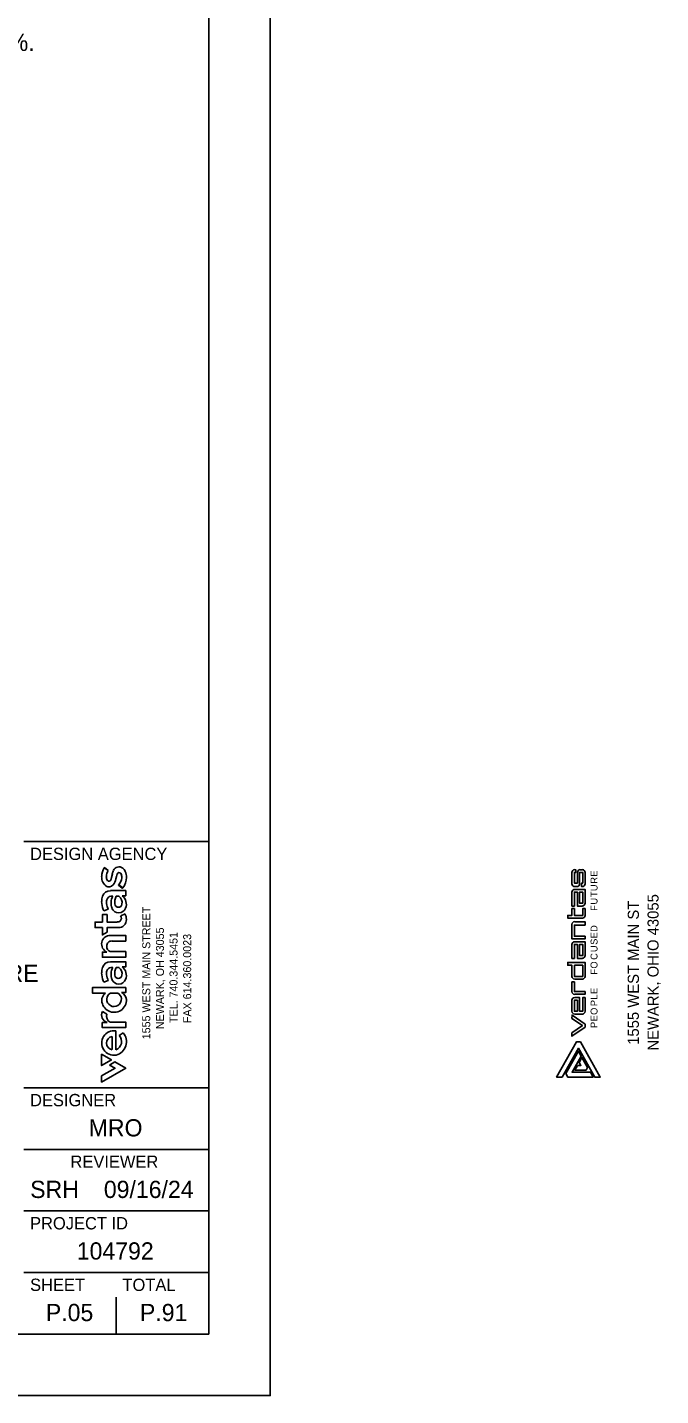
# Model space of a CAD drawing. Extents: x 0 to 46.4, y 0 to 22.
# Drawn here: x 32.03 to 37.17, y 0 to 11.11 of the extents above; entities that cross this region are included whole.
import ezdxf

# ---------------------------------------------------------------- set-up
doc = ezdxf.new("R2010")
doc.units = 0
for name, color, linetype in [('CS-ANNO-TTLB-LOGO', 7, 'Continuous'), ('Default', 7, 'Continuous'), ('SH_Border', 7, 'Continuous'), ('SH_Cut_Line', 7, 'Continuous'), ('SH_Data', 7, 'Continuous'), ('SH_Text', 7, 'Continuous')]:
    doc.layers.add(name, color=color, linetype=linetype)

msp = doc.modelspace()

# ---------------------------------------------------------------- linework, layer by layer
at = {"layer": 'CS-ANNO-TTLB-LOGO'}
for p, q in [((36.449, 4.249), (36.449, 4.156)), ((36.48, 4.271), (36.472, 4.271)), ((36.534, 4.271), (36.517, 4.271)), ((36.556, 4.156), (36.556, 4.249)), ((36.472, 4.134), (36.489, 4.134)), ((36.449, 3.976), (36.449, 4.089)), ((36.449, 3.551), (36.449, 3.664)), ((36.472, 3.383), (36.534, 3.383)), ((36.556, 3.121), (36.556, 3.233)), ((36.449, 3.211), (36.449, 3.121)), ((36.472, 3.098), (36.534, 3.098))]:
    msp.add_line(p, q, dxfattribs=at)
for points in [[(36.494, 4.249), (36.494, 4.162), (36.469, 4.162), (36.469, 4.249), (36.48, 4.249), (36.48, 4.271)], [(36.511, 4.156), (36.511, 4.249), (36.537, 4.249), (36.537, 4.162), (36.528, 4.162), (36.528, 4.134), (36.534, 4.134)], [(36.534, 3.976), (36.494, 3.976), (36.494, 4.089), (36.469, 4.089), (36.469, 3.976), (36.449, 3.976)], [(36.472, 4.111), (36.556, 4.111), (36.556, 3.999)], [(36.415, 3.9), (36.449, 3.9), (36.449, 3.956), (36.469, 3.956), (36.469, 3.9), (36.537, 3.9), (36.537, 3.956), (36.556, 3.956), (36.556, 3.9)], [(36.534, 3.878), (36.415, 3.878), (36.415, 3.9)], [(36.449, 3.827), (36.449, 3.709), (36.556, 3.709), (36.556, 3.731), (36.469, 3.731), (36.469, 3.821), (36.556, 3.821)], [(36.556, 3.821), (36.556, 3.849), (36.472, 3.849)], [(36.472, 3.686), (36.556, 3.686), (36.556, 3.574)], [(36.534, 3.551), (36.494, 3.551), (36.494, 3.664), (36.469, 3.664), (36.469, 3.551), (36.449, 3.551)], [(36.415, 3.518), (36.415, 3.495), (36.449, 3.495), (36.449, 3.405)], [(36.556, 3.405), (36.556, 3.518), (36.415, 3.518)], [(36.556, 3.281), (36.469, 3.281), (36.469, 3.36), (36.449, 3.36), (36.449, 3.281)], [(36.472, 3.259), (36.556, 3.259), (36.556, 3.281)], [(36.556, 3.233), (36.537, 3.233), (36.537, 3.121), (36.511, 3.121), (36.511, 3.233), (36.472, 3.233)]]:
    msp.add_lwpolyline(points, dxfattribs=at)
for points in [[(36.511, 4.089), (36.537, 4.089), (36.537, 3.999), (36.511, 3.999)], [(36.511, 3.664), (36.537, 3.664), (36.537, 3.574), (36.511, 3.574)], [(36.469, 3.495), (36.469, 3.405), (36.537, 3.405), (36.537, 3.495)], [(36.494, 3.211), (36.469, 3.211), (36.469, 3.121), (36.494, 3.121)], [(36.534, 3.005), (36.449, 2.946), (36.449, 2.918), (36.556, 2.993), (36.557, 3.016), (36.45, 3.091), (36.449, 3.064)]]:
    msp.add_lwpolyline(points, close=True, dxfattribs=at)
for centre, start, end in [((36.472, 4.249), 90, 180), ((36.517, 4.249), 90, 180), ((36.534, 4.249), 360, 90), ((36.472, 4.156), 180, 270), ((36.489, 4.156), 270, 0), ((36.534, 4.156), 270, 0), ((36.472, 4.089), 90, 180), ((36.534, 3.999), 270, 360), ((36.534, 3.9), 270, 360), ((36.472, 3.827), 90, 180), ((36.472, 3.664), 90, 180), ((36.534, 3.574), 270, 360), ((36.472, 3.405), 180, 270), ((36.534, 3.405), 270, 0), ((36.472, 3.281), 180, 270), ((36.472, 3.211), 90, 180), ((36.472, 3.121), 180, 270), ((36.534, 3.121), 270, 0)]:
    msp.add_arc(centre, 0.0225, start, end, dxfattribs=at)
at = {"layer": 'Default'}
for p, q in [((36.449, 4.249), (36.449, 4.156)), ((36.534, 4.271), (36.517, 4.271)), ((36.556, 4.156), (36.556, 4.249)), ((36.472, 4.134), (36.489, 4.134)), ((36.472, 3.383), (36.534, 3.383)), ((36.449, 3.211), (36.449, 3.121)), ((36.472, 3.098), (36.534, 3.098)), ((36.399, 2.615), (36.502, 2.798)), ((36.502, 2.798), (36.525, 2.758)), ((36.525, 2.758), (36.451, 2.626)), ((36.415, 2.587), (36.399, 2.615)), ((36.621, 2.587), (36.415, 2.587)), ((36.451, 2.626), (36.599, 2.626)), ((36.599, 2.626), (36.621, 2.587))]:
    msp.add_line(p, q, dxfattribs=at)
for points in [[(36.494, 4.249), (36.494, 4.162), (36.469, 4.162), (36.469, 4.249), (36.48, 4.249), (36.48, 4.271), (36.472, 4.271)], [(36.511, 4.156), (36.511, 4.249), (36.537, 4.249), (36.537, 4.162), (36.528, 4.162), (36.528, 4.134), (36.534, 4.134)], [(36.449, 4.089), (36.449, 3.976), (36.469, 3.976), (36.469, 4.089), (36.494, 4.089), (36.494, 3.976), (36.534, 3.976)], [(36.556, 3.999), (36.556, 4.111), (36.472, 4.111)], [(36.556, 3.9), (36.556, 3.956), (36.537, 3.956), (36.537, 3.9), (36.469, 3.9), (36.469, 3.956), (36.449, 3.956), (36.449, 3.9), (36.415, 3.9), (36.415, 3.878), (36.534, 3.878)], [(36.449, 3.827), (36.449, 3.709), (36.556, 3.709), (36.556, 3.731), (36.469, 3.731), (36.469, 3.821), (36.556, 3.821), (36.556, 3.849), (36.472, 3.849)], [(36.556, 3.574), (36.556, 3.686), (36.472, 3.686)], [(36.449, 3.664), (36.449, 3.551), (36.469, 3.551), (36.469, 3.664), (36.494, 3.664), (36.494, 3.551), (36.534, 3.551)], [(36.556, 3.405), (36.556, 3.518), (36.415, 3.518), (36.415, 3.495), (36.449, 3.495), (36.449, 3.405)], [(36.472, 3.259), (36.556, 3.259), (36.556, 3.281), (36.469, 3.281), (36.469, 3.36), (36.449, 3.36), (36.449, 3.281)], [(36.556, 3.121), (36.556, 3.233), (36.537, 3.233), (36.537, 3.121), (36.511, 3.121), (36.511, 3.233), (36.472, 3.233)]]:
    msp.add_lwpolyline(points, dxfattribs=at)
for points in [[(36.537, 4.089), (36.537, 3.999), (36.511, 3.999), (36.511, 4.089)], [(36.537, 3.664), (36.537, 3.574), (36.511, 3.574), (36.511, 3.664)], [(36.469, 3.495), (36.537, 3.495), (36.537, 3.405), (36.469, 3.405)], [(36.494, 3.211), (36.494, 3.121), (36.469, 3.121), (36.469, 3.211)], [(36.449, 2.946), (36.449, 2.918), (36.556, 2.993), (36.557, 3.016), (36.45, 3.091), (36.449, 3.064), (36.534, 3.005)], [(36.502, 2.821), (36.634, 2.587), (36.679, 2.587), (36.518, 2.872), (36.486, 2.872), (36.325, 2.587), (36.37, 2.587)], [(36.37, 2.587), (36.502, 2.821), (36.634, 2.587), (36.679, 2.587), (36.518, 2.872), (36.486, 2.872), (36.325, 2.587)], [(36.399, 2.615), (36.415, 2.587), (36.621, 2.587), (36.599, 2.626), (36.451, 2.626), (36.525, 2.758), (36.502, 2.798)], [(36.495, 2.682), (36.473, 2.643), (36.564, 2.643), (36.577, 2.666), (36.531, 2.746), (36.509, 2.706), (36.522, 2.682)], [(36.495, 2.682), (36.522, 2.682), (36.509, 2.706), (36.531, 2.746), (36.577, 2.666), (36.564, 2.643), (36.473, 2.643)]]:
    msp.add_lwpolyline(points, close=True, dxfattribs=at)
for centre, start, end in [((36.472, 4.249), 90, 180), ((36.517, 4.249), 90, 180), ((36.534, 4.249), 360, 90), ((36.472, 4.156), 180, 270), ((36.489, 4.156), 270, 0), ((36.534, 4.156), 270, 0), ((36.472, 4.089), 90, 180), ((36.534, 3.999), 270, 0), ((36.534, 3.9), 270, 0), ((36.472, 3.827), 90, 180), ((36.472, 3.664), 90, 180), ((36.534, 3.574), 270, 0), ((36.472, 3.405), 180, 270), ((36.534, 3.405), 270, 0), ((36.472, 3.281), 180, 270), ((36.472, 3.211), 90, 180), ((36.472, 3.121), 180, 270), ((36.534, 3.121), 270, 0)]:
    msp.add_arc(centre, 0.0225, start, end, dxfattribs=at)
at = {"layer": 'SH_Border'}
for p, q in [((32, 4.5), (33.5, 4.5)), ((32, 2.5), (33.5, 2.5)), ((32, 2), (33.5, 2)), ((32, 1.5), (33.5, 1.5)), ((32, 1), (33.5, 1))]:
    msp.add_line(p, q, dxfattribs=at)
msp.add_lwpolyline([(1.5, 21.5), (33.5, 21.5), (33.5, 0.5), (1.5, 0.5)], close=True, dxfattribs=at)
at = {"layer": 'SH_Cut_Line'}
msp.add_lwpolyline([(0, 0), (34, 0), (34, 22), (0, 22)], close=True, dxfattribs=at)
at = {"layer": 'SH_Data'}
for p, q in [((32.75, 3.5), (32.75, 3.5)), ((32.75, 0.5), (32.75, 0.8)), ((32.375, 0.675), (32.375, 0.675))]:
    msp.add_line(p, q, dxfattribs=at)
at = {"layer": 'SH_Text'}
for p, q in [((32.684, 4.264), (32.652, 4.287)), ((32.718, 4.238), (32.711, 4.207)), ((32.747, 4.196), (32.751, 4.216)), ((32.77, 4.148), (32.802, 4.124)), ((32.707, 4.056), (32.723, 4.056)), ((32.749, 4.056), (32.772, 4.056)), ((32.643, 3.948), (32.648, 3.936)), ((32.821, 3.912), (32.786, 3.896)), ((32.707, 3.477), (32.723, 3.477)), ((32.749, 3.477), (32.772, 3.477)), ((32.643, 3.369), (32.648, 3.357)), ((32.702, 3.269), (32.762, 3.269)), ((32.674, 3.098), (32.637, 3.12)), ((32.716, 2.917), (32.716, 2.81)), ((32.747, 2.809), (32.747, 2.962)), ((32.806, 2.947), (32.774, 2.925))]:
    msp.add_line(p, q, dxfattribs=at)
for points in [[(32.685, 4.266), (32.653, 4.289), (32.652, 4.287)], [(32.684, 4.264), (32.685, 4.266)], [(32.718, 4.238), (32.711, 4.207)], [(32.747, 4.196), (32.751, 4.216)], [(32.77, 4.148), (32.767, 4.146), (32.799, 4.121), (32.802, 4.124)], [(32.797, 4.059), (32.827, 4.059), (32.827, 4.101), (32.702, 4.101)], [(32.797, 4.059), (32.827, 4.059), (32.827, 4.101), (32.702, 4.101)], [(32.707, 4.056), (32.723, 4.056)], [(32.772, 4.056), (32.749, 4.056)], [(32.757, 3.846), (32.675, 3.846), (32.675, 3.907), (32.637, 3.907), (32.637, 3.846), (32.578, 3.846), (32.578, 3.801), (32.637, 3.801), (32.637, 3.741), (32.675, 3.765), (32.675, 3.801), (32.765, 3.801)], [(32.757, 3.846), (32.675, 3.846), (32.675, 3.907), (32.637, 3.907), (32.637, 3.846), (32.578, 3.846), (32.578, 3.801), (32.637, 3.801), (32.637, 3.741), (32.675, 3.765), (32.675, 3.801), (32.765, 3.801)], [(32.643, 3.948), (32.648, 3.936)], [(32.648, 3.936), (32.684, 3.95), (32.68, 3.96)], [(32.648, 3.936), (32.684, 3.95), (32.68, 3.96)], [(32.821, 3.912), (32.786, 3.896)], [(32.715, 3.692), (32.827, 3.692), (32.827, 3.737), (32.703, 3.737)], [(32.715, 3.692), (32.827, 3.692), (32.827, 3.737), (32.703, 3.737)], [(32.674, 3.602), (32.637, 3.602), (32.637, 3.56), (32.827, 3.56), (32.827, 3.606), (32.7, 3.606)], [(32.674, 3.602), (32.637, 3.602), (32.637, 3.56), (32.827, 3.56), (32.827, 3.606), (32.7, 3.606)], [(32.797, 3.481), (32.827, 3.481), (32.827, 3.523), (32.702, 3.523)], [(32.797, 3.481), (32.827, 3.481), (32.827, 3.523), (32.702, 3.523)], [(32.707, 3.477), (32.723, 3.477)], [(32.772, 3.477), (32.749, 3.477)], [(32.643, 3.369), (32.648, 3.357)], [(32.648, 3.357), (32.684, 3.372), (32.68, 3.381)], [(32.648, 3.357), (32.684, 3.372), (32.68, 3.381)], [(32.663, 3.269), (32.556, 3.269), (32.556, 3.314), (32.827, 3.314), (32.827, 3.273), (32.793, 3.273)], [(32.793, 3.273), (32.827, 3.273), (32.827, 3.314), (32.556, 3.314), (32.556, 3.269), (32.663, 3.269)], [(32.702, 3.269), (32.762, 3.269)], [(32.674, 3.098), (32.637, 3.12)], [(32.677, 3.03), (32.636, 3.03), (32.636, 2.989), (32.827, 2.989), (32.827, 3.033), (32.701, 3.033)], [(32.677, 3.03), (32.636, 3.03), (32.636, 2.989), (32.827, 2.989), (32.827, 3.033), (32.701, 3.033)], [(32.716, 2.81), (32.716, 2.917)], [(32.747, 2.809), (32.747, 2.962)], [(32.806, 2.947), (32.774, 2.925)], [(32.631, 2.772), (32.631, 2.681), (32.71, 2.727), (32.631, 2.772)], [(32.695, 2.685), (32.74, 2.659), (32.631, 2.597), (32.631, 2.547), (32.827, 2.659), (32.739, 2.71), (32.695, 2.685)]]:
    msp.add_lwpolyline(points, dxfattribs=at)
for points in [[(32.71, 2.727), (32.631, 2.681), (32.631, 2.772)], [(32.695, 2.685), (32.74, 2.659), (32.631, 2.597), (32.631, 2.547), (32.827, 2.659), (32.739, 2.71)]]:
    msp.add_lwpolyline(points, close=True, dxfattribs=at)
for centre, radius, start, end in [((32.763, 4.216), 0.131, 147.2233, 179.842), ((32.763, 4.216), 0.131, 147.2233, 179.842), ((32.764, 4.214), 0.0948, 148.1233, 178.1135), ((32.764, 4.214), 0.0948, 148.1233, 178.1135), ((32.844, 4.209), 0.13, 154.0447, 167.2149), ((32.844, 4.209), 0.13, 154.0447, 167.2149), ((32.772, 4.245), 0.0493, 52.7092, 154.2166), ((32.772, 4.245), 0.0493, 52.7092, 154.2166), ((32.845, 4.201), 0.0949, 158.1863, 170.6328), ((32.845, 4.201), 0.0949, 158.1863, 170.6328), ((32.773, 4.231), 0.0165, 26.9165, 163.602), ((32.773, 4.231), 0.0165, 26.9165, 163.602), ((32.729, 4.21), 0.0655, 357.0077, 26.3112), ((32.729, 4.21), 0.0655, 357.0077, 26.3112), ((32.757, 4.229), 0.0711, 22.8278, 50.7157), ((32.757, 4.229), 0.0711, 22.8278, 50.7157), ((32.712, 4.21), 0.12, 359.0192, 22.9257), ((32.712, 4.21), 0.12, 359.0192, 22.9257), ((32.745, 4.215), 0.114, 179.0109, 203.56), ((32.745, 4.215), 0.114, 179.0109, 203.56), ((32.703, 4.196), 0.067, 203.3692, 237.807), ((32.703, 4.196), 0.067, 203.3692, 237.807), ((32.69, 4.178), 0.0458, 238.9453, 317.6829), ((32.69, 4.178), 0.0458, 238.9453, 317.6829), ((32.739, 4.216), 0.0702, 179.0539, 195.6921), ((32.739, 4.216), 0.0702, 179.0539, 195.6921), ((32.704, 4.205), 0.0335, 193.8561, 223.7191), ((32.704, 4.205), 0.0335, 193.8561, 223.7191), ((32.691, 4.192), 0.0148, 224.7822, 330.4366), ((32.691, 4.192), 0.0148, 224.7822, 330.4366), ((32.631, 4.222), 0.0819, 332.9002, 349.3831), ((32.631, 4.222), 0.0819, 332.9002, 349.3831), ((32.644, 4.215), 0.105, 320.1259, 349.7023), ((32.644, 4.215), 0.105, 320.1259, 349.7023), ((32.701, 4.211), 0.0932, 317.363, 356.9244), ((32.701, 4.211), 0.0932, 317.363, 356.9244), ((32.703, 4.207), 0.129, 320.5166, 0.4341), ((32.703, 4.207), 0.129, 320.5166, 0.4341), ((32.76, 4.014), 0.128, 160.8128, 180.9317), ((32.76, 4.014), 0.128, 160.8128, 180.9317), ((32.83, 4.015), 0.199, 180.9467, 199.8354), ((32.83, 4.015), 0.199, 180.9467, 199.8354), ((32.7, 4.037), 0.0639, 88.076, 162.8642), ((32.7, 4.037), 0.0639, 88.076, 162.8642), ((32.735, 4.009), 0.0647, 163.2522, 179.9971), ((32.735, 4.009), 0.0647, 163.2522, 179.9971), ((32.822, 4.014), 0.152, 181.6616, 200.8714), ((32.822, 4.014), 0.152, 181.6616, 200.8714), ((32.709, 4.018), 0.0374, 92.9671, 165.223), ((32.709, 4.018), 0.0374, 92.9671, 165.223), ((32.815, 3.999), 0.108, 148.3497, 202.4708), ((32.815, 3.999), 0.108, 148.3497, 202.4708), ((32.843, 4.009), 0.105, 153.8372, 188.8746), ((32.843, 4.009), 0.105, 153.8372, 188.8746), ((32.733, 4.005), 0.0637, 348.1247, 52.3678), ((32.733, 4.005), 0.0637, 348.1247, 52.3678), ((32.746, 3.99), 0.0857, 338.2774, 53.7949), ((32.746, 3.99), 0.0857, 338.2774, 53.7949), ((32.77, 3.979), 0.0592, 201.6764, 339.7268), ((32.77, 3.979), 0.0592, 201.6764, 339.7268), ((32.767, 3.994), 0.0281, 182.327, 355.3778), ((32.767, 3.994), 0.0281, 182.327, 355.3778), ((32.748, 3.874), 0.0432, 1.8638, 29.9651), ((32.748, 3.874), 0.0432, 1.8638, 29.9651), ((32.738, 3.868), 0.0939, 359.5424, 28.2495), ((32.738, 3.868), 0.0939, 359.5424, 28.2495), ((32.76, 3.878), 0.0314, 265.0692, 356.3548), ((32.76, 3.878), 0.0314, 265.0692, 356.3548), ((32.768, 3.865), 0.0642, 267.8641, 1.6213), ((32.768, 3.865), 0.0642, 267.8641, 1.6213), ((32.701, 3.667), 0.0703, 88.9896, 246.9111), ((32.701, 3.667), 0.0703, 88.9896, 246.9111), ((32.716, 3.651), 0.0434, 137.3049, 182.9688), ((32.716, 3.651), 0.0434, 137.3049, 182.9688), ((32.713, 3.649), 0.0433, 86.9739, 132.7421), ((32.713, 3.649), 0.0433, 86.9739, 132.7421), ((32.72, 3.649), 0.0477, 180.3466, 244.9113), ((32.72, 3.649), 0.0477, 180.3466, 244.9113), ((32.76, 3.435), 0.128, 160.8128, 180.9317), ((32.76, 3.435), 0.128, 160.8128, 180.9317), ((32.7, 3.459), 0.0639, 88.076, 162.8642), ((32.7, 3.459), 0.0639, 88.076, 162.8642), ((32.735, 3.431), 0.0647, 163.2522, 179.9971), ((32.735, 3.431), 0.0647, 163.2522, 179.9971), ((32.709, 3.44), 0.0374, 92.9671, 165.223), ((32.709, 3.44), 0.0374, 92.9671, 165.223), ((32.815, 3.42), 0.108, 148.3497, 202.4708), ((32.815, 3.42), 0.108, 148.3497, 202.4708), ((32.843, 3.431), 0.105, 153.8372, 188.8746), ((32.843, 3.431), 0.105, 153.8372, 188.8746), ((32.733, 3.427), 0.0637, 348.1247, 52.3678), ((32.733, 3.427), 0.0637, 348.1247, 52.3678), ((32.746, 3.412), 0.0857, 338.2774, 53.7949), ((32.746, 3.412), 0.0857, 338.2774, 53.7949), ((32.83, 3.437), 0.199, 180.9467, 199.8354), ((32.83, 3.437), 0.199, 180.9467, 199.8354), ((32.822, 3.435), 0.152, 181.6616, 200.8714), ((32.822, 3.435), 0.152, 181.6616, 200.8714), ((32.77, 3.401), 0.0592, 201.6764, 339.7268), ((32.77, 3.401), 0.0592, 201.6764, 339.7268), ((32.767, 3.416), 0.0281, 182.327, 355.3778), ((32.767, 3.416), 0.0281, 182.327, 355.3778), ((32.703, 3.21), 0.0714, 124.2843, 181.2723), ((32.703, 3.21), 0.0714, 124.2843, 181.2723), ((32.731, 3.218), 0.0586, 119.9007, 175.5797), ((32.731, 3.218), 0.0586, 119.9007, 175.5797), ((32.732, 3.219), 0.0595, 176.4529, 5.055), ((32.732, 3.219), 0.0595, 176.4529, 5.055), ((32.733, 3.218), 0.0588, 6.0666, 60.041), ((32.733, 3.218), 0.0588, 6.0666, 60.041), ((32.765, 3.212), 0.0671, 5.3084, 64.5252), ((32.765, 3.212), 0.0671, 5.3084, 64.5252), ((32.693, 3.091), 0.0628, 152.6524, 255.2929), ((32.693, 3.091), 0.0628, 152.6524, 255.2929), ((32.732, 3.213), 0.1, 182.7719, 2.9779), ((32.732, 3.213), 0.1, 182.7719, 2.9779), ((32.726, 3.081), 0.0545, 162.1384, 242.0408), ((32.726, 3.081), 0.0545, 162.1384, 242.0408), ((32.731, 2.864), 0.0996, 81.0446, 280.2577), ((32.731, 2.864), 0.0996, 81.0446, 280.2577), ((32.725, 2.863), 0.0543, 98.8378, 261.1622), ((32.725, 2.863), 0.0543, 98.8378, 261.1622), ((32.721, 2.876), 0.072, 290.9232, 42.7391), ((32.721, 2.876), 0.072, 290.9232, 42.7391), ((32.718, 2.875), 0.114, 285.6668, 39.3699), ((32.718, 2.875), 0.114, 285.6668, 39.3699)]:
    msp.add_arc(centre, radius, start, end, dxfattribs=at)

# ---------------------------------------------------------------- texts
at = {"layer": 'Default'}
for s, p in [('E', (36.657, 4.214)), ('R', (36.657, 4.158)), ('U', (36.657, 4.097)), ('T', (36.657, 4.049)), ('U', (36.657, 3.988)), ('F', (36.657, 3.937)), ('D', (36.657, 3.766)), ('S', (36.657, 3.661)), ('E', (36.657, 3.714)), ('C', (36.657, 3.539)), ('U', (36.657, 3.602)), ('O', (36.657, 3.468)), ('F', (36.657, 3.419)), ('E', (36.657, 3.261)), ('L', (36.657, 3.216)), ('O', (36.657, 3.092)), ('P', (36.657, 3.163)), ('E', (36.657, 3.039)), ('P', (36.657, 2.986))]:
    msp.add_text(s, height=0.0563, rotation=90, dxfattribs=at).set_placement(p)
at = {"layer": 'SH_Data'}
for s, height, p in [('DESIGN AGENCY', 0.1, (32.05, 4.35)), ('DESIGNER', 0.1, (32.05, 2.35)), ('MRO', 0.14, (32.526, 2.105)), ('REVIEWER', 0.1, (32.378, 1.85)), ('SRH', 0.14, (32.051, 1.605)), ('09/16/24', 0.14, (32.649, 1.605)), ('PROJECT ID', 0.1, (32.05, 1.35)), ('104792', 0.14, (32.429, 1.105)), ('SHEET', 0.1, (32.05, 0.85)), ('TOTAL', 0.1, (32.8, 0.85)), ('P.05', 0.14, (32.178, 0.605)), ('P.91', 0.14, (32.942, 0.605))]:
    msp.add_text(s, height=height, dxfattribs=at).set_placement(p)
at = {"layer": 'SH_Text'}
for s, p in [('RATE UTILIZED SHALL BE PER THE MIX DESIGN, OR PER DEFAULT VALUE OF 5%.', (24.66, 10.92)), ('ALLOW THE CHEMICALLY STABILIZED SUBGRADE TO FREEZE DURING THE CURE ', (24.66, 3.36))]:
    msp.add_text(s, height=0.14, dxfattribs=at).set_placement(p)
for s, height, p in [('1555 WEST MAIN ST', 0.09, (36.993, 2.849)), ('NEWARK, OHIO 43055', 0.09, (37.153, 2.802)), ('1555 WEST MAIN STREET', 0.06497, (33.026, 2.894)), ('NEWARK, OH 43055', 0.06497, (33.137, 2.976)), ('TEL. 740.344.5451', 0.06497, (33.247, 3.026)), ('FAX 614.360.0023', 0.06497, (33.358, 3.025))]:
    msp.add_text(s, height=height, rotation=90, dxfattribs=at).set_placement(p)

doc.saveas('drawing.dxf')
